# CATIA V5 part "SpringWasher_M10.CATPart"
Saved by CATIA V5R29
Part number: SpringWasher_M10
Source: Unknown
Bounding box of the stored display mesh (mm): x -9.2 to 9.2, y -9.2 to 9.199, z -1.25 to 1.25
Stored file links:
  C:\가치같이\SmartFactory_BoxErectorConveyor\Boxing(over)\SpringWasher_M10.CATPart
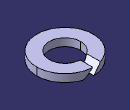
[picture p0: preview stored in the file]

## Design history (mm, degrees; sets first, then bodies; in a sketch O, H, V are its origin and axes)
Body1 (main body)
  Solid1 "PartBody": solid without history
